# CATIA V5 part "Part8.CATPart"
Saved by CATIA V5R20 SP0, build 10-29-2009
Part number: 3JT12.5X2.5X17.5
Revision: ANY
Definition: UNKNOWN
Nomenclature: 3JT12.5X2.5X17.5
Source: Unknown
Bounding box of the stored display mesh (mm): x -8.75 to 8.75, y -1.25 to 1.25, z -8.75 to 8.75
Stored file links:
  C:\Users\Utente\Desktop\IO LAVORO\3D X SITO CF\CUMSA\3D files PW\pw101630\pw101630_injection\Part8.CATPart
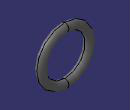
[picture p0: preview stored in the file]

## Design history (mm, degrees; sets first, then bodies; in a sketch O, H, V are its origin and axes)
Body1 "Revolución1" (main body)
  Solid1: solid without history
